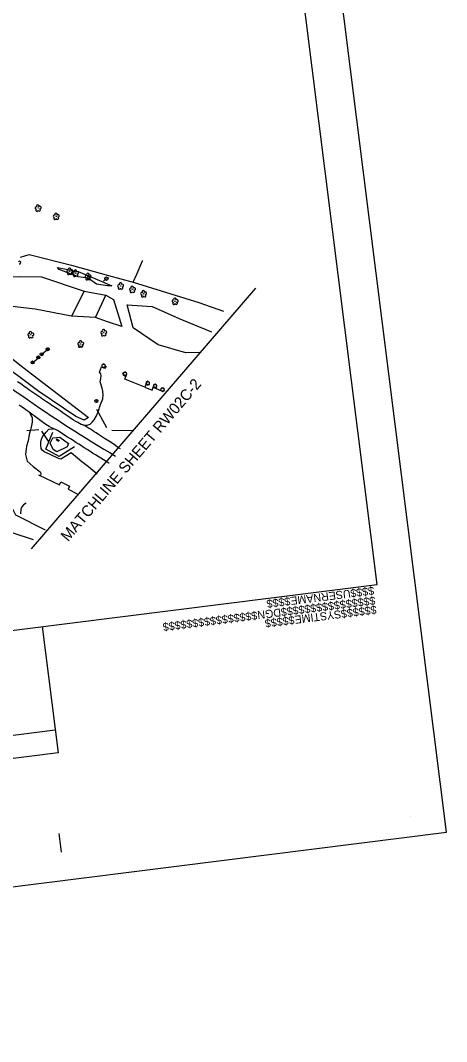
# Model space of a CAD drawing. Extents: x 477009 to 479892, y 492858 to 496862.
# Drawn here: x 479272 to 479892, y 492858 to 494341 of the extents above; entities that cross this region are included whole.
import ezdxf

# ---------------------------------------------------------------- set-up
doc = ezdxf.new("R2010")
doc.units = 0
for name, color, linetype in [('CTL Sheet Border CELL', 7, 'Continuous'), ('Exist Horizontal Alignment', 7, 'Continuous'), ('Exist Other Culture Area Outline', 7, 'Continuous'), ('Exist Other Culture Fence Line', 7, 'Continuous'), ('Exist Other Culture Gate', 7, 'Continuous'), ('Exist Other Culture Sign', 7, 'Continuous'), ('Exist Other Culture Sign Post CELL', 7, 'Continuous'), ('Exist Roads EOP', 7, 'Continuous'), ('Exist Roads Soil', 7, 'Continuous'), ('Exist Structure Major Bridge WW', 7, 'Continuous'), ('Exist Structure Minor Head and End Wall', 7, 'Continuous'), ('Exist Utilities Other Located Object CELL', 7, 'Continuous'), ('Exist Utilities Power Pole CELL', 7, 'Continuous'), ('Exist Vegetation Hedge Row', 7, 'Continuous'), ('Exist Vegetation Shrub CELL', 7, 'Continuous'), ('Exist Vegetation Tree CELL', 7, 'Continuous'), ('Exist Vegetation Woods Line', 7, 'Continuous'), ('Matchline', 7, 'Continuous'), ('Matchline Text', 7, 'Continuous'), ('Sheet Block Revision CELL', 7, 'Continuous'), ('Sheet Plot Border Outside CELL', 7, 'Continuous')]:
    doc.layers.add(name, color=color, linetype=linetype)

msp = doc.modelspace()

# ---------------------------------------------------------------- linework, layer by layer
at = {"layer": 'CTL Sheet Border CELL'}
for p, q in [((479790.9, 493521.7), (479790.9, 493521.7)), ((479790.9, 493521.7), (479790.9, 493521.7)), ((479790.9, 493521.7), (479790.9, 493521.7)), ((479790.9, 493521.7), (479790.9, 493521.7)), ((479790.9, 493521.7), (479790.9, 493521.7)), ((479790.9, 493521.7), (479790.9, 493521.7)), ((479790.9, 493521.7), (479790.9, 493521.7)), ((479790.9, 493521.7), (479790.9, 493521.7)), ((479790.9, 493521.7), (479790.9, 493521.7)), ((479790.9, 493521.7), (479790.9, 493521.7)), ((479790.9, 493521.7), (479790.9, 493521.7)), ((479839.1, 493184), (479839.1, 493184)), ((479332.1, 493132.5), (479328.6, 493160)), ((479892, 493161.7), (479892, 493161.7))]:
    msp.add_line(p, q, dxfattribs=at)
msp.add_lwpolyline([(477068.9, 496527.4), (477483.7, 493231.4), (479790.9, 493521.7), (479376.1, 496817.7)], close=True, dxfattribs=at)
msp.add_lwpolyline([(479780.5, 493604.1), (479780.5, 493604.1)], dxfattribs=at)
msp.add_lwpolyline([(479780.5, 493604.1), (479780.5, 493604.1)], dxfattribs=at)
at = {"layer": 'Exist Horizontal Alignment'}
msp.add_arc((480448.9, 495467.9), 2043, 230.4653, 239.4639, dxfattribs=at)
at = {"layer": 'Exist Other Culture Area Outline'}
for points in [[(479456.5, 493815.9), (479453.4, 493808.4), (479424.3, 493819.8), (479427.3, 493827.2)], [(479298.9, 493680.9), (479298.9, 493681), (479329.3, 493666.7), (479331.3, 493670.8), (479343.8, 493664.5), (479341.7, 493660.2), (479356.9, 493652.6)], [(479280.8, 493639.8), (479276.8, 493637.6), (479274.4, 493634.6), (479273.2, 493631.3), (479272.7, 493624.2)]]:
    msp.add_lwpolyline(points, dxfattribs=at)
at = {"layer": 'Exist Other Culture Fence Line'}
for points in [[(479285.2, 494001.2), (479346.9, 493985.7), (479400.4, 493970.9), (479436.3, 493960.8), (479531.7, 493931.4), (479567.8, 493918.8)], [(479436.3, 493960.8), (479441.7, 493972.8), (479450.1, 493992.1), (479450.3, 493992.6)], [(479351, 493721.7), (479328.6, 493707.9), (479309.6, 493718.1), (479319.6, 493742.9)]]:
    msp.add_lwpolyline(points, dxfattribs=at)
at = {"layer": 'Exist Other Culture Gate'}
for p, q in [((479272.6, 493997.4), (479285.2, 494001.2)), ((479398.3, 493749.5), (479383.6, 493775.8)), ((479299.2, 493746.4), (479281.8, 493745.1)), ((479313.3, 493730), (479303.4, 493744.4)), ((479435.3, 493745), (479405.2, 493745.4))]:
    msp.add_line(p, q, dxfattribs=at)
at = {"layer": 'Exist Other Culture Sign'}
for p, q in [((479314.3, 493865.1), (479302.1, 493854.4)), ((479300.6, 493852.3), (479289.1, 493842.4))]:
    msp.add_line(p, q, dxfattribs=at)
at = {"layer": 'Exist Other Culture Sign Post CELL'}
for centre, radius in [((479312.1, 493863.5), 2.18), ((479312.1, 493863.5), 0.24), ((479290.1, 493844.3), 2.18), ((479290.1, 493844.3), 0.24), ((479298.6, 493851.6), 2.18), ((479298.6, 493851.6), 0.24), ((479303.4, 493856.3), 2.18), ((479303.4, 493856.3), 0.24)]:
    msp.add_circle(centre, radius, dxfattribs=at)
at = {"layer": 'Exist Roads EOP'}
for points in [[(479418.1, 493718.8), (479413.7, 493721.4), (479410.5, 493723.5), (479405.8, 493726.9), (479402.1, 493729.3), (479399.6, 493730.9), (479394.7, 493734), (479390.2, 493736.9), (479385.8, 493739.8), (479382.6, 493741.9), (479379.9, 493743.6), (479377.2, 493745.5), (479374.4, 493747.3), (479371.6, 493749), (479367, 493751.8), (479363.4, 493753.7), (479362.9, 493753.9), (479361.3, 493754.2), (479360.7, 493754.4), (479355.8, 493757), (479353.1, 493758.7), (479349.9, 493760.7), (479344.9, 493763.9), (479341.4, 493766.2), (479337.7, 493768.6), (479334, 493771.1), (479330.1, 493773.8), (479325.7, 493776.8), (479320.7, 493780.2), (479318.2, 493781.9), (479315.6, 493783.7), (479313, 493785.5), (479310.3, 493787.3), (479307.6, 493789.1), (479304.8, 493791), (479302.1, 493792.9), (479299.2, 493794.9), (479296.4, 493796.8), (479293.5, 493798.8), (479290.5, 493800.8), (479287.6, 493802.8), (479284.9, 493804.7), (479282.4, 493806.5), (479277.7, 493809.8), (479273, 493813.1), (479268.4, 493816.4)], [(479401.3, 493698), (479401.1, 493698.2), (479397.2, 493700.5), (479393.3, 493702.9), (479389.4, 493705.3), (479385.4, 493707.7), (479381.5, 493710.2), (479377.5, 493712.7), (479373.5, 493715.2), (479369.4, 493717.8), (479365.3, 493720.4), (479361.3, 493723), (479357.2, 493725.6), (479353.1, 493728.1), (479349, 493730.7), (479345.1, 493733.3), (479341.1, 493735.8), (479337.3, 493738.2), (479333.8, 493740.5), (479328.8, 493743.8), (479326.2, 493745.5), (479323.6, 493747.1), (479320, 493748.5), (479317.6, 493749.5), (479314.4, 493751.3), (479309.4, 493754.4), (479306.1, 493756.7), (479302.4, 493759.4), (479298.5, 493762.3), (479294.4, 493765.2), (479292.6, 493766.6), (479289.5, 493768.9), (479286.8, 493771), (479282.5, 493774.2), (479278.6, 493777), (479273.7, 493780.4), (479270.9, 493782.3)]]:
    msp.add_lwpolyline(points, dxfattribs=at)
at = {"layer": 'Exist Roads Soil'}
for points in [[(479365.1, 493753), (479369.6, 493753.1), (479373.9, 493754.6), (479376.9, 493757.4), (479379.6, 493760.8), (479382.9, 493767), (479385.4, 493772.7), (479389, 493783.2), (479392.1, 493791.3), (479392.9, 493797.2), (479392.2, 493802.5), (479391.3, 493807), (479388.3, 493816.1), (479389.5, 493821.1), (479389.9, 493825), (479389.4, 493827.7), (479387.5, 493830.4), (479390.4, 493838), (479395.9, 493836), (479397.8, 493838.7)], [(479425.9, 493823.8), (479424.4, 493825), (479421.8, 493827.6), (479421.6, 493828.6), (479421.9, 493829.3)], [(479453.4, 493808.4), (479463.8, 493804), (479465.4, 493808.2), (479477.4, 493803.3)], [(479285.5, 493771.4), (479289.4, 493764.1), (479289.7, 493760.2), (479289.6, 493757.7), (479288.7, 493752.9), (479287, 493746.5), (479285.3, 493739.5), (479284, 493730.3), (479281.5, 493722.7), (479279.9, 493710.7), (479282.5, 493700.7), (479291, 493692.9), (479301.1, 493685.4), (479302.4, 493683.6), (479301.5, 493679.6)], [(479384, 493682.1), (479371.6, 493692.7), (479361.7, 493699.8), (479346.4, 493713.2), (479331.3, 493703.7), (479328.1, 493704.6), (479314.7, 493711.1), (479306.8, 493714.3), (479303.9, 493717.1), (479302.7, 493719.4), (479302.2, 493723.9), (479302.1, 493728.7), (479303.1, 493732.9), (479305.2, 493737.3), (479309.8, 493743.2), (479314, 493747.2), (479320, 493747.9)]]:
    msp.add_lwpolyline(points, dxfattribs=at)
at = {"layer": 'Exist Structure Major Bridge WW'}
for p, q in [((479324.7, 493732.6), (479328.3, 493730)), ((479325.3, 493733.4), (479328.9, 493730.8))]:
    msp.add_line(p, q, dxfattribs=at)
at = {"layer": 'Exist Structure Minor Head and End Wall'}
for p, q in [((479324.7, 493732.6), (479325.3, 493733.4)), ((479328.9, 493730.8), (479328.3, 493730))]:
    msp.add_line(p, q, dxfattribs=at)
at = {"layer": 'Exist Utilities Other Located Object CELL'}
for radius in [2.18, 0.24]:
    msp.add_circle((479382.9, 493788.4), radius, dxfattribs=at)
at = {"layer": 'Exist Utilities Power Pole CELL'}
for q in [(479393.3, 493962.3), (479397.5, 493966.1)]:
    msp.add_line((479397.5, 493966.1), q, dxfattribs=at)
msp.add_circle((479397.5, 493966.1), 2.45, dxfattribs=at)
at = {"layer": 'Exist Vegetation Hedge Row'}
for p, q in [((479365.3, 493947.9), (479396.6, 493942.1)), ((479381.6, 493909.7), (479346.7, 493911.7))]:
    msp.add_line(p, q, dxfattribs=at)
for points in [[(479326.5, 493982.1), (479356.3, 493976.6), (479384.2, 493964.8), (479405.3, 493955.7), (479399.1, 493955.6), (479383, 493957.9), (479370.8, 493966.6), (479356.6, 493968.6), (479328.9, 493979.3), (479326.5, 493982.1)], [(479171.8, 493921.6), (479214.7, 493885.9), (479276, 493837.3), (479371.7, 493764.5), (479365.4, 493760.7), (479353.2, 493765.9), (479299.4, 493802.3), (479233.3, 493850.9), (479191.1, 493882.6), (479162.8, 493909.3), (479163, 493921), (479171.8, 493921.6)], [(479315.9, 493726.8), (479319.8, 493735), (479329.8, 493735.8), (479342.3, 493726.4), (479340.4, 493721.7), (479325.2, 493714.4), (479320.1, 493717.6), (479315.9, 493726.8)], [(479247.1, 493659.5), (479265.4, 493623.1), (479308.4, 493601.3)]]:
    msp.add_lwpolyline(points, dxfattribs=at)
at = {"layer": 'Exist Vegetation Shrub CELL'}
for p, q in [((479393.4, 493839.1), (479393.4, 493839.1)), ((479424.4, 493827.5), (479424.4, 493827.5)), ((479457.6, 493814.1), (479457.6, 493814.1)), ((479468.2, 493809.9), (479468.2, 493809.9)), ((479479.1, 493804.8), (479479.1, 493804.8))]:
    msp.add_line(p, q, dxfattribs=at)
for centre, radius, start, end in [((479391.6, 493838.4), 0.955, 95.1099, 327.9534), ((479391.9, 493840.3), 0.968, 35.8908, 245.4216), ((479393.3, 493837.5), 0.984, 151.2797, 21.387), ((479393.6, 493841.2), 0.99, 334.8391, 200.4717), ((479395, 493838.2), 0.937, 204.9913, 73.4601), ((479395.1, 493840), 0.929, 284.4567, 126.0861), ((479424.6, 493829.5), 0.99, 334.8391, 200.4717), ((479422.6, 493826.8), 0.955, 95.1099, 327.9534), ((479422.9, 493828.6), 0.968, 35.8908, 245.4216), ((479424.3, 493825.8), 0.984, 151.2797, 21.387), ((479426, 493826.6), 0.937, 204.9913, 73.4601), ((479426.1, 493828.3), 0.929, 284.4567, 126.0861), ((479456.1, 493815.2), 0.968, 35.8908, 245.4216), ((479457.8, 493816.1), 0.99, 334.8391, 200.4717), ((479459.3, 493814.9), 0.929, 284.4567, 126.0861), ((479455.8, 493813.4), 0.955, 95.1099, 327.9534), ((479457.5, 493812.4), 0.984, 151.2797, 21.387), ((479459.2, 493813.1), 0.937, 204.9913, 73.4601), ((479466.4, 493809.2), 0.955, 95.1099, 327.9534), ((479466.7, 493811), 0.968, 35.8908, 245.4216), ((479468, 493808.2), 0.984, 151.2797, 21.387), ((479468.4, 493811.9), 0.99, 334.8391, 200.4717), ((479469.8, 493808.9), 0.937, 204.9913, 73.4601), ((479469.8, 493810.7), 0.929, 284.4567, 126.0861), ((479477.3, 493804.1), 0.955, 95.1099, 327.9534), ((479477.7, 493805.9), 0.968, 35.8908, 245.4216), ((479479, 493803.1), 0.984, 151.2797, 21.387), ((479479.4, 493806.8), 0.99, 334.8391, 200.4717), ((479480.8, 493803.8), 0.937, 204.9913, 73.4601), ((479480.8, 493805.6), 0.929, 284.4567, 126.0861)]:
    msp.add_arc(centre, radius, start, end, dxfattribs=at)
at = {"layer": 'Exist Vegetation Tree CELL'}
for p, q in [((479298.3, 494068.7), (479298.3, 494068.7)), ((479324.6, 494056.6), (479324.6, 494056.6)), ((479344.2, 493976.7), (479344.2, 493976.7)), ((479352.8, 493974.1), (479352.8, 493974.1)), ((479370.7, 493969.2), (479370.7, 493969.2)), ((479418.1, 493955.4), (479418.1, 493955.4)), ((479435.3, 493950.6), (479435.3, 493950.6)), ((479451.6, 493944.1), (479451.6, 493944.1)), ((479497.4, 493933.2), (479497.4, 493933.2)), ((479287.6, 493884.6), (479287.6, 493884.6)), ((479393.6, 493887.6), (479393.6, 493887.6)), ((479360.1, 493871.2), (479360.1, 493871.2))]:
    msp.add_line(p, q, dxfattribs=at)
for centre in [(479298.3, 494068.7), (479324.6, 494056.6), (479344.2, 493976.7), (479352.8, 493974.1), (479370.7, 493969.2), (479418.1, 493955.4), (479435.3, 493950.6), (479451.6, 493944.1), (479497.4, 493933.2), (479287.6, 493884.6), (479393.6, 493887.6), (479360.1, 493871.2)]:
    msp.add_circle(centre, 0.326, dxfattribs=at)
for centre, radius, start, end in [((479295.7, 494068.8), 1.73, 62.6636, 279.3457), ((479296.6, 494065.5), 1.69, 111.5671, 6.231), ((479297.9, 494071.5), 1.86, 330.1651, 219.7134), ((479299.9, 494065.8), 1.7, 181.2822, 74.56), ((479300.8, 494069.3), 1.9, 257.1011, 134.1999), ((479322, 494056.7), 1.73, 62.6636, 279.3457), ((479322.9, 494053.5), 1.69, 111.5671, 6.231), ((479324.2, 494059.5), 1.86, 330.1651, 219.7134), ((479326.3, 494053.7), 1.7, 181.2822, 74.56), ((479327.2, 494057.2), 1.9, 257.1011, 134.1999), ((479271.1, 493989.4), 1.9, 257.1011, 134.1999), ((479341.6, 493976.9), 1.73, 62.6636, 279.3457), ((479343.8, 493979.6), 1.86, 330.1651, 219.7134), ((479346.7, 493977.3), 1.9, 257.1011, 134.1999), ((479352.4, 493976.9), 1.86, 330.1651, 219.7134), ((479342.5, 493973.6), 1.69, 111.5671, 6.231), ((479345.8, 493973.8), 1.7, 181.2822, 74.56), ((479350.2, 493974.2), 1.73, 62.6636, 279.3457), ((479351.1, 493970.9), 1.69, 111.5671, 6.231), ((479354.5, 493971.2), 1.7, 181.2822, 74.56), ((479355.3, 493974.6), 1.9, 257.1011, 134.1999), ((479368.1, 493969.3), 1.73, 62.6636, 279.3457), ((479369, 493966), 1.69, 111.5671, 6.231), ((479370.4, 493972), 1.86, 330.1651, 219.7134), ((479372.4, 493966.3), 1.7, 181.2822, 74.56), ((479373.3, 493969.8), 1.9, 257.1011, 134.1999), ((479415.5, 493955.5), 1.73, 62.6636, 279.3457), ((479416.4, 493952.3), 1.69, 111.5671, 6.231), ((479417.7, 493958.3), 1.86, 330.1651, 219.7134), ((479419.8, 493952.5), 1.7, 181.2822, 74.56), ((479420.7, 493956), 1.9, 257.1011, 134.1999), ((479432.7, 493950.7), 1.73, 62.6636, 279.3457), ((479433.6, 493947.4), 1.69, 111.5671, 6.231), ((479434.9, 493953.4), 1.86, 330.1651, 219.7134), ((479437, 493947.7), 1.7, 181.2822, 74.56), ((479437.9, 493951.1), 1.9, 257.1011, 134.1999), ((479451.2, 493947), 1.86, 330.1651, 219.7134), ((479449, 493944.2), 1.73, 62.6636, 279.3457), ((479449.9, 493941), 1.69, 111.5671, 6.231), ((479453.3, 493941.2), 1.7, 181.2822, 74.56), ((479454.1, 493944.7), 1.9, 257.1011, 134.1999), ((479494.8, 493933.4), 1.73, 62.6636, 279.3457), ((479497, 493936.1), 1.86, 330.1651, 219.7134), ((479499.9, 493933.8), 1.9, 257.1011, 134.1999), ((479495.7, 493930.1), 1.69, 111.5671, 6.231), ((479499, 493930.3), 1.7, 181.2822, 74.56), ((479287.2, 493887.5), 1.86, 330.1651, 219.7134), ((479391, 493887.8), 1.73, 62.6636, 279.3457), ((479393.2, 493890.5), 1.86, 330.1651, 219.7134), ((479396.1, 493888.2), 1.9, 257.1011, 134.1999), ((479285, 493884.8), 1.73, 62.6636, 279.3457), ((479285.9, 493881.5), 1.69, 111.5671, 6.231), ((479289.3, 493881.7), 1.7, 181.2822, 74.56), ((479290.1, 493885.2), 1.9, 257.1011, 134.1999), ((479359.7, 493874.1), 1.86, 330.1651, 219.7134), ((479391.9, 493884.5), 1.69, 111.5671, 6.231), ((479395.3, 493884.7), 1.7, 181.2822, 74.56), ((479357.5, 493871.4), 1.73, 62.6636, 279.3457), ((479358.4, 493868.1), 1.69, 111.5671, 6.231), ((479361.8, 493868.3), 1.7, 181.2822, 74.56), ((479362.7, 493871.8), 1.9, 257.1011, 134.1999)]:
    msp.add_arc(centre, radius, start, end, dxfattribs=at)
at = {"layer": 'Exist Vegetation Woods Line'}
for points in [[(479182.2, 493968.7), (479221.7, 493967.5), (479271.4, 493969.4), (479303.3, 493968.5), (479365.3, 493947.9)], [(479346.7, 493911.7), (479294.1, 493921.8), (479247.7, 493927), (479230.3, 493918.9), (479222.8, 493922.2), (479213.8, 493934.9), (479202.8, 493937.4), (479182.2, 493968.7)], [(479365.3, 493947.9), (479346.7, 493911.7)], [(479396.6, 493942.1), (479407.9, 493935.8), (479419.9, 493896.4), (479399.3, 493903.3), (479381.6, 493909.7)], [(479381.6, 493909.7), (479396.6, 493942.1)], [(479533.3, 493858.6), (479512.9, 493858.3), (479472.7, 493869.9), (479436.5, 493894.7), (479427.9, 493927.9), (479464.1, 493925.8), (479504.1, 493907.7), (479550.4, 493888.9)], [(479155.4, 493778.5), (479241.5, 493731.3), (479246.2, 493687.7), (479247.1, 493659.5), (479243.8, 493625.1), (479259.8, 493597.2), (479290.9, 493587.2)]]:
    msp.add_lwpolyline(points, dxfattribs=at)
at = {"layer": 'Matchline'}
msp.add_line((479288.4, 493573.4), (479614.6, 493952.4), dxfattribs=at)
at = {"layer": 'Sheet Block Revision CELL'}
for p, q in [((479304.2, 493460.5), (479327.3, 493277)), ((479323.2, 493309.9), (477586.3, 493091.3)), ((479327.3, 493277), (477590.5, 493058.4))]:
    msp.add_line(p, q, dxfattribs=at)
at = {"layer": 'Sheet Plot Border Outside CELL'}
msp.add_lwpolyline([(479892, 493161.7), (479426.4, 496862), (477009.3, 496557.8), (477475, 492857.5)], close=True, dxfattribs=at)

# ---------------------------------------------------------------- texts
at = {"layer": 'CTL Sheet Border CELL'}
for s, p in [('$$$$USERNAME$$$$', (479786, 493518.7)), ('$$$$$$$$$$$$$$$$DGN$$$$$$$$$$$$$$$$', (479787.8, 493504.3)), ('$$$$$$SYSTIME$$$$$', (479789.5, 493491))]:
    msp.add_text(s, height=11.627, rotation=187.1725, dxfattribs=at).set_placement(p)
at = {"layer": 'Matchline Text'}
msp.add_text('MATCHLINE SHEET RW02C-2', height=16, rotation=49.6634, dxfattribs=at).set_placement((479341.8, 493583))

doc.saveas('drawing.dxf')
